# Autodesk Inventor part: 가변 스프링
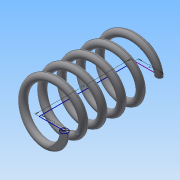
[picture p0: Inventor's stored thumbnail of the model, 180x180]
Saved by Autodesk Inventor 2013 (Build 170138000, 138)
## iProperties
Created: 2019-10
Part Number: 가변 스프링
Material: 일반
Document SubType Name: Modeling
Designer: Administrator
Density: 1 g/cm^3
Mass: 18.293 g
Surface Area: 124.166 cm^2
Volume: 18.293 cm^3
Author: Administrator
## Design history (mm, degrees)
sketch "스케치1"
  geometry: L1 (0, 0)-(21, 0); L2 (0, 0)-(0, 67.25); L3 (0, 67.25)-(21, 67.25); C1 r 3 at (21, 0)
  constraints: 6 end point, 2 perpendicular, 1 centre point, 1 coincident, 1 horizontal
  dimensions: "d0" = 21 distance of L1.start L1.end; "d1" = 67.25 distance of L1.start L2.end (derived); "d2" = 21 distance of L2.end L3.end; "d3" = 6 diameter of C1
feature "코일1" pitch "d4" = 10; turns "d6" = 5; dims "d5" = 67.25 (= d1), "d7" = 0, angle "d8" = 90 deg, angle "d9" = 90 deg, "d10" = 0, "d11" = 0
sketch "스케치2"
  geometry: L1 (0, 25)-(67.25, 25); L2 (67.25, 25)-(67.25, -25); L3 (67.25, -25)-(0, -25); L4 (0, -25)-(0, 25); 2 further points
  constraints: 8 end point, 2 parallel, 1 coincident, 1 horizontal, 1 midpoint, 1 perpendicular
  dimensions: "d12" = 67.25 distance of L1.start L1.end (= d1); "d14" = 50 distance of L1.end L2.end
extrude "돌출1" sketch "스케치2" stored distance "d15" = 0; taper "d16" = 0 deg
node "솔리드1"
